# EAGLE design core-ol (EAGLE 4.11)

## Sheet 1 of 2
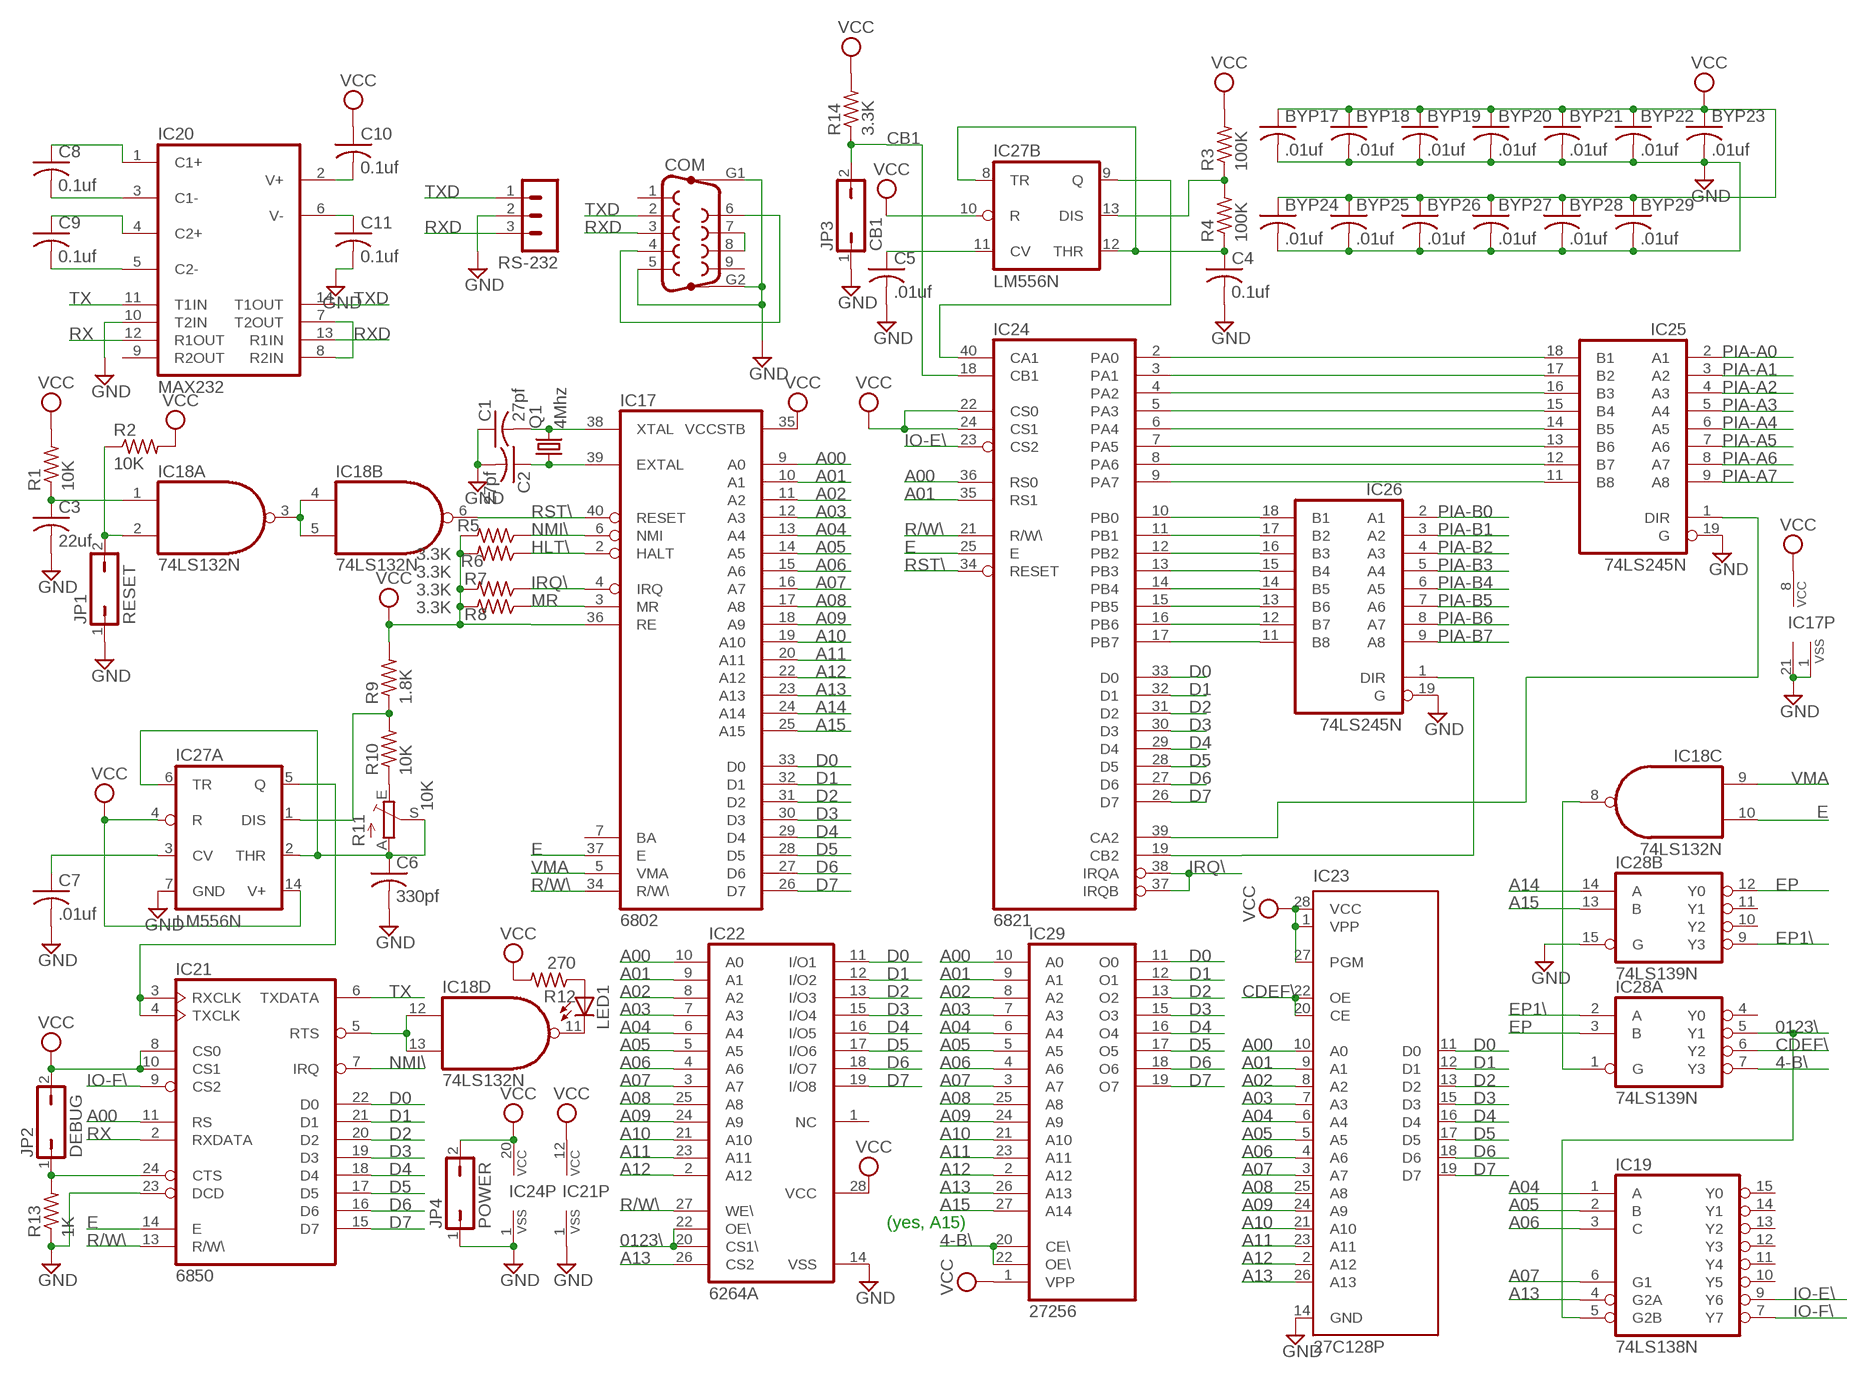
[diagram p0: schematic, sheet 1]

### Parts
BYP17  .01uf  C-US050-025X075  [C050-025X075]
BYP18  .01uf  C-US050-025X075  [C050-025X075]
BYP19  .01uf  C-US050-025X075  [C050-025X075]
BYP20  .01uf  C-US050-025X075  [C050-025X075]
BYP21  .01uf  C-US050-025X075  [C050-025X075]
BYP22  .01uf  C-US050-025X075  [C050-025X075]
BYP23  .01uf  C-US050-025X075  [C050-025X075]
BYP24  .01uf  C-US050-025X075  [C050-025X075]
BYP25  .01uf  C-US050-025X075  [C050-025X075]
BYP26  .01uf  C-US050-025X075  [C050-025X075]
BYP27  .01uf  C-US050-025X075  [C050-025X075]
BYP28  .01uf  C-US050-025X075  [C050-025X075]
BYP29  .01uf  C-US050-025X075  [C050-025X075]
C1  27pf  C-US050-025X075  [C050-025X075]
C2  27pf  C-US050-025X075  [C050-025X075]
C3  22uf  C-US102-043X133  [C102-043X133]
C4  0.1uf  C-US050-025X075  [C050-025X075]
C5  .01uf  C-US050-025X075  [C050-025X075]
C6  330pf  C-US050-025X075  [C050-025X075]
C7  .01uf  C-US050-025X075  [C050-025X075]
C8  0.1uf  C-US050-025X075  [C050-025X075]
C9  0.1uf  C-US050-025X075  [C050-025X075]
C10  0.1uf  C-US050-025X075  [C050-025X075]
C11  0.1uf  C-US050-025X075  [C050-025X075]
COM  F09HP  [F09HP]
IC17  6802  [DIL40]
IC18  74LS132N  74LS00N  [DIL14]
IC19  74LS138N  [DIL16]
IC20  MAX232  [DIL16]
IC21  6850  [DIL24]
IC22  6264A  [DIL28-6]
IC23  27C128P  [DIL28-6]
IC24  6821  [DIL40]
IC25  74LS245N  [DIL20]
IC26  74LS245N  [DIL20]
IC27  LM556N  [DIL14]
IC28  74LS139N  [DIL16]
IC29  27256  [DIL28]
JP1  RESET  JP1Q  [JP1]
JP2  DEBUG  JP1Q  [JP1]
JP3  CB1  JP1Q  [JP1]
JP4  POWER  JP1Q  [JP1]
LED1  LED3MM  [LED3MM]
Q1  4Mhz  CRYTALHC18U-V  [HC18U-V]
R1  10K  R-US_0207/7  [0207/7]
R2  10K  R-US_0207/7  [0207/7]
R3  100K  R-US_0207/7  [0207/7]
R4  100K  R-US_0207/7  [0207/7]
R5  3.3K  R-US_0207/7  [0207/7]
R6  3.3K  R-US_0207/7  [0207/7]
R7  3.3K  R-US_0207/7  [0207/7]
R8  3.3K  R-US_0207/7  [0207/7]
R9  1.8K  R-US_0207/7  [0207/7]
R10  10K  R-US_0207/7  [0207/7]
R11  10K  TRIM_EU-B90P  [SP19L]
R12  270  R-US_0207/7  [0207/7]
R13  1K  R-US_0207/7  [0207/7]
R14  3.3K  R-US_0207/7  [0207/7]
RS-232  MA03-1  [MA03-1]

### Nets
4-B\: IC28.7(A:Y3) IC29.20(CE\) IC29.22(OE\)
0123\: IC19.5(G2B) IC22.20(CS1\) IC22.22(OE\) IC28.5(A:Y1)
A00: IC17.9(A0) IC21.11(RS) IC22.10(A0) IC23.10(A0) IC24.36(RS0) IC29.10(A0)
A01: IC17.10(A1) IC22.9(A1) IC23.9(A1) IC24.35(RS1) IC29.9(A1)
A02: IC17.11(A2) IC22.8(A2) IC23.8(A2) IC29.8(A2)
A03: IC17.12(A3) IC22.7(A3) IC23.7(A3) IC29.7(A3)
A04: IC17.13(A4) IC19.1(A) IC22.6(A4) IC23.6(A4) IC29.6(A4)
A05: IC17.14(A5) IC19.2(B) IC22.5(A5) IC23.5(A5) IC29.5(A5)
A06: IC17.15(A6) IC19.3(C) IC22.4(A6) IC23.4(A6) IC29.4(A6)
A07: IC17.16(A7) IC19.6(G1) IC22.3(A7) IC23.3(A7) IC29.3(A7)
A08: IC17.17(A8) IC22.25(A8) IC23.25(A8) IC29.25(A8)
A09: IC17.18(A9) IC22.24(A9) IC23.24(A9) IC29.24(A9)
A10: IC17.19(A10) IC22.21(A10) IC23.21(A10) IC29.21(A10)
A11: IC17.20(A11) IC22.23(A11) IC23.23(A11) IC29.23(A11)
A12: IC17.22(A12) IC22.2(A12) IC23.2(A12) IC29.2(A12)
A13: IC17.23(A13) IC19.4(G2A) IC22.26(CS2) IC23.26(A13) IC29.26(A13)
A14: IC17.24(A14) IC28.14(B:A)
A15: IC17.25(A15) IC28.13(B:B) IC29.27(A14)
CB1: IC24.18(CB1) JP3.2 R14.1
CDEF\: IC23.20(CE) IC23.22(OE) IC28.6(A:Y2)
D0: IC17.33(D0) IC21.22(D0) IC22.11(I/O1) IC23.11(D0) IC24.33(D0) IC29.11(O0)
D1: IC17.32(D1) IC21.21(D1) IC22.12(I/O2) IC23.12(D1) IC24.32(D1) IC29.12(O1)
D2: IC17.31(D2) IC21.20(D2) IC22.13(I/O3) IC23.13(D2) IC24.31(D2) IC29.13(O2)
D3: IC17.30(D3) IC21.19(D3) IC22.15(I/O4) IC23.15(D3) IC24.30(D3) IC29.15(O3)
D4: IC17.29(D4) IC21.18(D4) IC22.16(I/O5) IC23.16(D4) IC24.29(D4) IC29.16(O4)
D5: IC17.28(D5) IC21.17(D5) IC22.17(I/O6) IC23.17(D5) IC24.28(D5) IC29.17(O5)
D6: IC17.27(D6) IC21.16(D6) IC22.18(I/O7) IC23.18(D6) IC24.27(D6) IC29.18(O6)
D7: IC17.26(D7) IC21.15(D7) IC22.19(I/O8) IC23.19(D7) IC24.26(D7) IC29.19(O7)
E: IC17.37(E) IC18.10(C:I1) IC21.14(E) IC24.25(E)
EP: IC28.3(A:B) IC28.12(B:Y0)
EP1\: IC28.2(A:A) IC28.9(B:Y3)
GND [Power]: BYP17.2 BYP18.2 BYP19.2 BYP20.2 BYP21.2 BYP22.2 BYP23.2 BYP24.2 BYP25.2 BYP26.2 BYP27.2 BYP28.2 BYP29.2 C1.1 C2.2 C3.2 C4.2 C5.2 C6.2 C7.2 C11.2 COM.5 COM.G1 COM.G2 IC17.1(VSS) IC17.21(VSS) IC20.10(T2IN) IC21.1(VSS) IC21.23(DCD) IC22.14(VSS) IC23.14(GND) IC24.1(VSS) IC25.19(G) IC26.19(G) IC27.7(A:GND) IC28.15(B:G) JP1.1 JP3.1 JP4.1 R13.1 RS-232.2 ; also sheet 2
HLT\: IC17.2(HALT) R5.1
IO-E\: IC19.9(Y6) IC24.23(CS2)
IO-F\: IC19.7(Y7) IC21.9(CS2)
IRQ\: IC17.4(IRQ) IC24.37(IRQB) IC24.38(IRQA) R7.1
MR: IC17.3(MR) R8.1
N$1: COM.4 COM.6
N$3: C2.1 IC17.39(EXTAL) Q1.1
N$4: C1.2 IC17.38(XTAL) Q1.2
N$5: IC24.2(PA0) IC25.18(B1)
N$6: IC18.3(A:O) IC18.4(B:I0) IC18.5(B:I1)
N$21: C3.1 IC18.1(A:I0) R1.1
N$22: IC18.2(A:I1) JP1.2 R2.1
N$23: IC21.3(RXCLK) IC21.4(TXCLK) IC27.5(A:Q)
N$24: IC24.10(PB0) IC26.18(B1)
N$25: IC24.11(PB1) IC26.17(B2)
N$27: C6.1 IC27.2(A:THR) IC27.6(A:TR) R11.A R11.S
N$28: IC27.1(A:DIS) R9.1 R10.2
N$94: IC24.12(PB2) IC26.16(B3)
N$124: IC24.13(PB3) IC26.15(B4)
N$125: IC24.14(PB4) IC26.14(B5)
N$126: IC24.15(PB5) IC26.13(B6)
N$127: IC24.16(PB6) IC26.12(B7)
N$128: IC24.17(PB7) IC26.11(B8)
N$129: IC24.3(PA1) IC25.17(B2)
N$130: IC24.4(PA2) IC25.16(B3)
N$131: IC24.5(PA3) IC25.15(B4)
N$132: IC24.6(PA4) IC25.14(B5)
N$133: IC24.7(PA5) IC25.13(B6)
N$134: IC24.8(PA6) IC25.12(B7)
N$135: IC24.9(PA7) IC25.11(B8)
N$136: IC24.19(CB2) IC26.1(DIR)
N$137: IC24.39(CA2) IC25.1(DIR)
N$138: IC24.40(CA1) IC27.9(B:Q)
N$140: C4.1 IC27.8(B:TR) IC27.12(B:THR) R4.1
N$141: IC27.13(B:DIS) R3.1 R4.2
N$142: C5.1 IC27.11(B:CV)
N$143: R10.1 R11.E
N$145: COM.7 COM.8
N$147: IC18.12(D:I0) IC18.13(D:I1) IC21.5(RTS)
N$148: IC18.11(D:O) LED1.K(C)
N$149: LED1.A R12.1
N$150: IC21.24(CTS) JP2.1 R13.2
N$151: IC18.8(C:O) IC28.1(A:G)
N$153: IC20.7(T2OUT) IC20.8(R2IN)
N$154: C7.1 IC27.3(A:CV)
N$155: C9.2 IC20.5(C2-)
N$156: C9.1 IC20.4(C2+)
N$157: C8.2 IC20.3(C1-)
N$158: C8.1 IC20.1(C1+)
N$159: C11.1 IC20.6(V-)
N$160: C10.2 IC20.2(V+)
NMI\: IC17.6(NMI) IC21.7(IRQ) R6.1
PIA-A0: IC25.2(A1) ; also sheet 2
PIA-A1: IC25.3(A2) ; also sheet 2
PIA-A2: IC25.4(A3) ; also sheet 2
PIA-A3: IC25.5(A4) ; also sheet 2
PIA-A4: IC25.6(A5) ; also sheet 2
PIA-A5: IC25.7(A6) ; also sheet 2
PIA-A6: IC25.8(A7) ; also sheet 2
PIA-A7: IC25.9(A8) ; also sheet 2
PIA-B0: IC26.2(A1) ; also sheet 2
PIA-B1: IC26.3(A2) ; also sheet 2
PIA-B2: IC26.4(A3) ; also sheet 2
PIA-B3: IC26.5(A4) ; also sheet 2
PIA-B4: IC26.6(A5) ; also sheet 2
PIA-B5: IC26.7(A6) ; also sheet 2
PIA-B6: IC26.8(A7) ; also sheet 2
PIA-B7: IC26.9(A8) ; also sheet 2
R/W\: IC17.34(R/W\) IC21.13(R/W\) IC22.27(WE\) IC24.21(R/W\)
RST\: IC17.40(RESET) IC18.6(B:O) IC24.34(RESET)
RX: IC20.12(R1OUT) IC21.2(RXDATA)
RXD: COM.3 IC20.13(R1IN) RS-232.3
TX: IC20.11(T1IN) IC21.6(TXDATA)
TXD: COM.2 IC20.14(T1OUT) RS-232.1
VCC [Power]: BYP17.1 BYP18.1 BYP19.1 BYP20.1 BYP21.1 BYP22.1 BYP23.1 BYP24.1 BYP25.1 BYP26.1 BYP27.1 BYP28.1 BYP29.1 C10.1 IC17.8(VCC) IC17.35(VCCSTB) IC17.36(RE) IC21.8(CS0) IC21.10(CS1) IC21.12(VCC) IC22.28(VCC) IC23.1(VPP) IC23.27(PGM) IC23.28(VCC) IC24.20(VCC) IC24.22(CS0) IC24.24(CS1) IC27.4(A:R) IC27.10(B:R) IC27.14(A:V+) IC29.1(VPP) JP2.2 JP4.2 R1.2 R2.2 R3.2 R5.2 R6.2 R7.2 R8.2 R9.2 R12.2 R14.2 ; also sheet 2
VMA: IC17.5(VMA) IC18.9(C:I0)
Unconnected: COM.1 COM.9 IC17.7(BA) IC19.10(Y5) IC19.11(Y4) IC19.12(Y3) IC19.13(Y2) IC19.14(Y1) IC19.15(Y0) IC20.9(R2OUT) IC22.1(NC) IC28.4(A:Y0) IC28.10(B:Y2) IC28.11(B:Y1)

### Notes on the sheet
- (yes, A15)

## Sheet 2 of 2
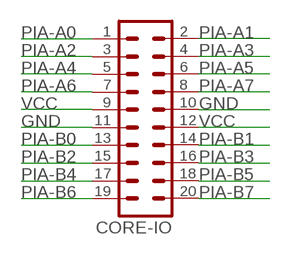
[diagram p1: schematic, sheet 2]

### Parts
CORE-IO  MA10-2  [MA10-2]

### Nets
GND [Power]: CORE-IO.10 CORE-IO.11 ; also sheet 1
PIA-A0: CORE-IO.1 ; also sheet 1
PIA-A1: CORE-IO.2 ; also sheet 1
PIA-A2: CORE-IO.3 ; also sheet 1
PIA-A3: CORE-IO.4 ; also sheet 1
PIA-A4: CORE-IO.5 ; also sheet 1
PIA-A5: CORE-IO.6 ; also sheet 1
PIA-A6: CORE-IO.7 ; also sheet 1
PIA-A7: CORE-IO.8 ; also sheet 1
PIA-B0: CORE-IO.13 ; also sheet 1
PIA-B1: CORE-IO.14 ; also sheet 1
PIA-B2: CORE-IO.15 ; also sheet 1
PIA-B3: CORE-IO.16 ; also sheet 1
PIA-B4: CORE-IO.17 ; also sheet 1
PIA-B5: CORE-IO.18 ; also sheet 1
PIA-B6: CORE-IO.19 ; also sheet 1
PIA-B7: CORE-IO.20 ; also sheet 1
VCC [Power]: CORE-IO.9 CORE-IO.12 ; also sheet 1

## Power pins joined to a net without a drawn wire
GND: IC18.7(P:GND) IC19.8(GND) IC20.15(GND) IC25.10(GND) IC26.10(GND) IC28.8(P:GND) IC29.14(GND)
VCC: IC18.14(P:VCC) IC19.16(VCC) IC20.16(VCC) IC25.20(VCC) IC26.20(VCC) IC28.16(P:VCC) IC29.28(VCC)

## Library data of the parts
BYP17-BYP29 C1-C11 = rcl:C-US: CAPACITOR, American symbol
COM = con-subd:F09HP: SUB-D
CORE-IO = con-lstb:MA10-2: PIN HEADER
IC17 = micro-motorola:6802: MICROCONTROLLER/MEMORY DEVICE
IC18 = 74xx-us:74*00: Quad 2-input NAND gate
IC19 = 74xx-us:74*138: 3-line to 8-line DECODER/DEMULTIPLEXER
IC20 = maxim:MAX232: RS232 TRANSEIVER
IC21 = micro-motorola:6850: MICROCONTROLLER/MEMORY DEVICE
IC22 = memory-hitachi:6264A: MEMORY
IC23 = microchip:27*128: CMOS EPROM 128 K (16 K x 8)
IC24 = micro-motorola:6821: MICROCONTROLLER/MEMORY DEVICE
IC25 IC26 = 74xx-us:74*245: Octal BUS TRANSCEIVER, 3-state
IC27 = linear:*556: Dual TIMER
IC28 = 74xx-us:74*139: Dual 2-line to 4-line DECODER/DEMULTIPLEXER
IC29 = memory:27256: MEMORY
JP1-JP4 = jumper:JP1Q: JUMPER
LED1 = led:LED: LED
Q1 = crystal:CRYTAL: CRYSTAL
R1-R10 R12-R14 = rcl:R-US_: RESISTOR, American symbol
R11 = pot:TRIM_EU-: POTENTIOMETER
RS-232 = con-lstb:MA03-1: PIN HEADER

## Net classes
1 Power: width 0.508 mm, drill 0.254 mm, clearance 0.254 mm

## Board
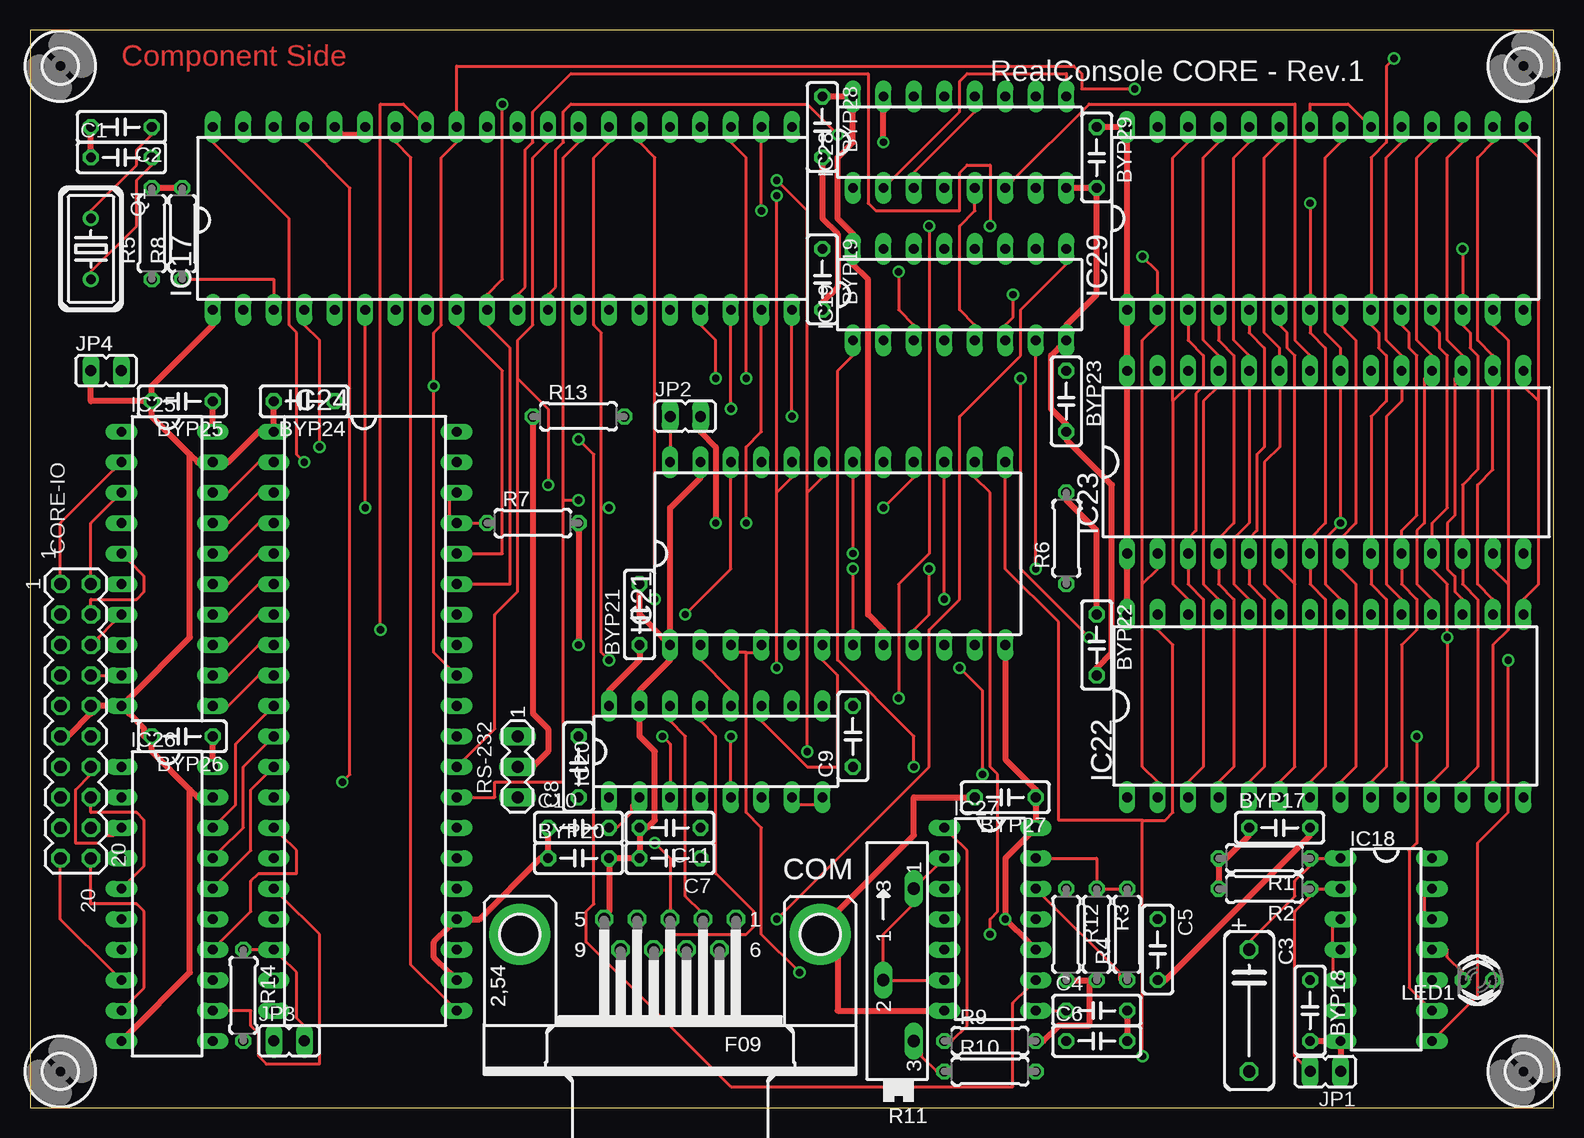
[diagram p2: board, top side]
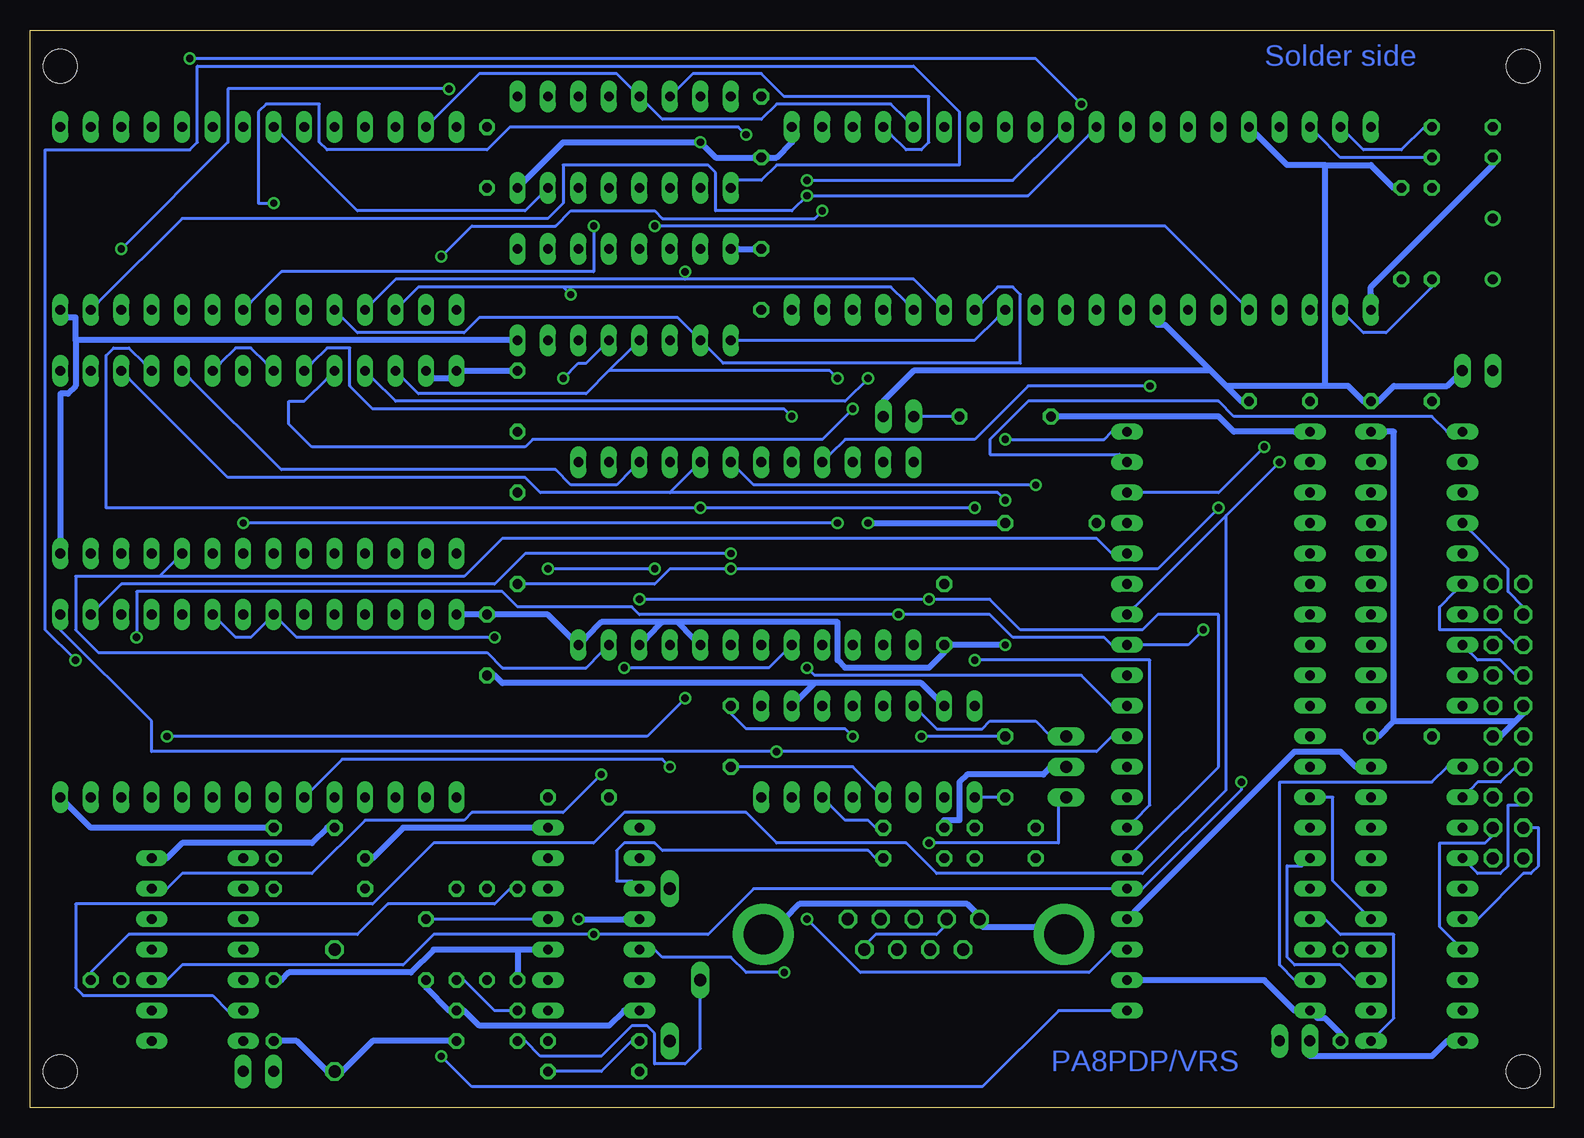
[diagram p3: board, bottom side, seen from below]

Size 126.98 x 89.84 mm. Coordinates in mm from the lower left corner, seen from the top.
Outline: 0,0 126.98,0 126.98,89.84 0,89.84 0,0
Copper layers (1*16): Top 0.035mm / dielectric 1.5mm / Bottom 0.035mm
Design rules "olimex10mil": minimum track width 10mil, minimum drill 24mil, track to track 10mil, track to pad 10mil, pad to pad 10mil, via to via 10mil, smd to smd 10mil, copper to edge 40mil, drill to drill 10mil, minimum pad ring 10mil, minimum via ring 8mil, stop-mask expansion 0mil, vias tented up to drill 0mil, thermal gap 10mil

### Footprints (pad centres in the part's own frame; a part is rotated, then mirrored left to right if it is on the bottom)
C050-025X075 = drill 0.813 octagon: 1 -2.54,0; 2 2.54,0
C102-043X133 = drill 1.016 octagon: 1 -5.08,0; 2 5.08,0
F09HP = drill 1.016 octagon: 1 -5.486,-1.27; 2 -2.743,-1.27; 3 0,-1.27; 4 2.743,-1.27; 5 5.486,-1.27; 6 -4.115,1.27; 7 -1.372,1.27; 8 1.372,1.27; 9 4.115,1.27 | drill 3.302 pad 5.08 round: G1 -12.522,0; G2 12.522,0
MA10-2 = drill 1.016 octagon: 1 -11.43,-1.27; 2 -11.43,1.27; 3 -8.89,-1.27; 4 -8.89,1.27; 5 -6.35,-1.27; 6 -6.35,1.27; 7 -3.81,-1.27; 8 -3.81,1.27; 9 -1.27,-1.27; 10 -1.27,1.27; 11 1.27,-1.27; 12 1.27,1.27; 13 3.81,-1.27; 14 3.81,1.27; 15 6.35,-1.27; 16 6.35,1.27; 17 8.89,-1.27; 18 8.89,1.27; 19 11.43,-1.27; 20 11.43,1.27
DIL40 = drill 0.813 long: 1 -24.13,-7.62; 2 -21.59,-7.62; 3 -19.05,-7.62; 4 -16.51,-7.62; 5 -13.97,-7.62; 6 -11.43,-7.62; 7 -8.89,-7.62; 8 -6.35,-7.62; 9 -3.81,-7.62; 10 -1.27,-7.62; 11 1.27,-7.62; 12 3.81,-7.62; 13 6.35,-7.62; 14 8.89,-7.62; 15 11.43,-7.62; 16 13.97,-7.62; 17 16.51,-7.62; 18 19.05,-7.62; 19 21.59,-7.62; 20 24.13,-7.62; 21 24.13,7.62; 22 21.59,7.62; 23 19.05,7.62; 24 16.51,7.62; 25 13.97,7.62; 26 11.43,7.62; 27 8.89,7.62; 28 6.35,7.62; 29 3.81,7.62; 30 1.27,7.62; 31 -1.27,7.62; 32 -3.81,7.62; 33 -6.35,7.62; 34 -8.89,7.62; 35 -11.43,7.62; 36 -13.97,7.62; 37 -16.51,7.62; 38 -19.05,7.62; 39 -21.59,7.62; 40 -24.13,7.62
DIL14 = drill 0.813 long: 1 -7.62,-3.81; 2 -5.08,-3.81; 3 -2.54,-3.81; 4 0,-3.81; 5 2.54,-3.81; 6 5.08,-3.81; 7 7.62,-3.81; 8 7.62,3.81; 9 5.08,3.81; 10 2.54,3.81; 11 0,3.81; 12 -2.54,3.81; 13 -5.08,3.81; 14 -7.62,3.81
DIL16 = drill 0.813 long: 1 -8.89,-3.81; 2 -6.35,-3.81; 3 -3.81,-3.81; 4 -1.27,-3.81; 5 1.27,-3.81; 6 3.81,-3.81; 7 6.35,-3.81; 8 8.89,-3.81; 9 8.89,3.81; 10 6.35,3.81; 11 3.81,3.81; 12 1.27,3.81; 13 -1.27,3.81; 14 -3.81,3.81; 15 -6.35,3.81; 16 -8.89,3.81
DIL24 = drill 0.813 long: 1 -13.97,-7.62; 2 -11.43,-7.62; 3 -8.89,-7.62; 4 -6.35,-7.62; 5 -3.81,-7.62; 6 -1.27,-7.62; 7 1.27,-7.62; 8 3.81,-7.62; 9 6.35,-7.62; 10 8.89,-7.62; 11 11.43,-7.62; 12 13.97,-7.62; 13 13.97,7.62; 14 11.43,7.62; 15 8.89,7.62; 16 6.35,7.62; 17 3.81,7.62; 18 1.27,7.62; 19 -1.27,7.62; 20 -3.81,7.62; 21 -6.35,7.62; 22 -8.89,7.62; 23 -11.43,7.62; 24 -13.97,7.62
DIL28-6 = drill 0.813 long: 1 -16.51,-7.62; 2 -13.97,-7.62; 3 -11.43,-7.62; 4 -8.89,-7.62; 5 -6.35,-7.62; 6 -3.81,-7.62; 7 -1.27,-7.62; 8 1.27,-7.62; 9 3.81,-7.62; 10 6.35,-7.62; 11 8.89,-7.62; 12 11.43,-7.62; 13 13.97,-7.62; 14 16.51,-7.62; 15 16.51,7.62; 16 13.97,7.62; 17 11.43,7.62; 18 8.89,7.62; 19 6.35,7.62; 20 3.81,7.62; 21 1.27,7.62; 22 -1.27,7.62; 23 -3.81,7.62; 24 -6.35,7.62; 25 -8.89,7.62; 26 -11.43,7.62; 27 -13.97,7.62; 28 -16.51,7.62
DIL20 = drill 0.813 long: 1 -11.43,-3.81; 2 -8.89,-3.81; 3 -6.35,-3.81; 4 -3.81,-3.81; 5 -1.27,-3.81; 6 1.27,-3.81; 7 3.81,-3.81; 8 6.35,-3.81; 9 8.89,-3.81; 10 11.43,-3.81; 11 11.43,3.81; 12 8.89,3.81; 13 6.35,3.81; 14 3.81,3.81; 15 1.27,3.81; 16 -1.27,3.81; 17 -3.81,3.81; 18 -6.35,3.81; 19 -8.89,3.81; 20 -11.43,3.81
DIL28 = drill 0.813 long: 1 -16.51,-7.62; 2 -13.97,-7.62; 3 -11.43,-7.62; 4 -8.89,-7.62; 5 -6.35,-7.62; 6 -3.81,-7.62; 7 -1.27,-7.62; 8 1.27,-7.62; 9 3.81,-7.62; 10 6.35,-7.62; 11 8.89,-7.62; 12 11.43,-7.62; 13 13.97,-7.62; 14 16.51,-7.62; 15 16.51,7.62; 16 13.97,7.62; 17 11.43,7.62; 18 8.89,7.62; 19 6.35,7.62; 20 3.81,7.62; 21 1.27,7.62; 22 -1.27,7.62; 23 -3.81,7.62; 24 -6.35,7.62; 25 -8.89,7.62; 26 -11.43,7.62; 27 -13.97,7.62; 28 -16.51,7.62
JP1 = drill 0.914 long: 1 0,-1.27; 2 0,1.27
LED3MM = drill 0.813 octagon: A -1.27,0; K 1.27,0
HC18U-V = drill 0.813 round: 1 -2.54,0; 2 2.54,0
0207/7 = drill 0.813 octagon: 1 -3.81,0; 2 3.81,0
SP19L = drill 1.016 long: A 5.715,-1.27; E -6.985,-1.27; S -1.905,1.27
MA03-1 = drill 1.016 long: 1 -2.54,0; 2 0,0; 3 2.54,0
2,8 = hole 2.8: 0,0

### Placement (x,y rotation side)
BYP17  104.14,23.33 0 top
BYP18  106.68,8.09 270 top
BYP19  66.04,69.05 270 top
BYP20  45.71,20.79 0 top
BYP21  50.79,41.11 90 top
BYP22  88.9,38.57 270 top
BYP23  86.36,58.89 270 top
BYP24  22.86,58.89 180 top
BYP25  12.69,58.89 180 top
BYP26  12.69,30.95 180 top
BYP27  81.28,25.87 180 top
BYP28  66.04,81.75 270 top
BYP29  88.9,79.21 270 top
C1  7.62,79.21 0 top
C2  7.62,81.75 180 top
C3  101.59,8.09 270 top
C4  88.9,8.09 0 top
C5  93.98,13.17 270 top
C6  88.9,5.55 0 top
C7  53.34,20.79 180 top
C8  45.71,28.41 90 top
C9  68.58,30.95 90 top
C10  45.71,23.33 0 top
C11  53.34,23.33 180 top
COM  53.34,14.44 180 top
CORE-IO  3.81,32.22 270 top
IC17  39.36,74.13 0 top
IC18  113.03,13.17 270 top
IC19  77.47,67.78 0 top
IC20  57.14,29.68 0 top
IC21  67.31,46.19 0 top
IC22  107.95,33.49 0 top
IC23  107.95,53.81 0 top
IC24  27.94,32.22 270 top
IC25  11.42,44.92 270 top
IC26  11.42,16.98 270 top
IC27  80.01,15.71 270 top
IC28  77.47,80.48 0 top
IC29  107.95,74.13 0 top
JP1  107.95,3.01 90 top
JP2  54.6,57.62 270 top
JP3  21.59,5.55 270 top
JP4  6.34,61.43 270 top
LED1  120.65,10.63 180 top
Q1  5.08,71.59 270 top
R1  102.87,20.79 180 top
R2  102.87,18.25 180 top
R3  88.9,14.44 270 top
R4  91.44,14.44 90 top
R5  10.15,72.86 90 top
R6  86.36,47.46 90 top
R7  41.9,48.73 0 top
R8  12.69,72.86 90 top
R9  80.01,5.55 0 top
R10  80.01,3.01 0 top
R11  72.39,12.54 90 top
R12  86.36,14.44 270 top
R13  45.71,57.62 0 top
R14  17.78,9.36 270 top
RS-232  40.63,28.41 270 top
U$3  [2,8]  2.54,86.83 0 top
U$4  [2,8]  2.54,3.01 0 top
U$5  [2,8]  124.45,86.83 0 top
U$6  [2,8]  124.45,3.01 0 top

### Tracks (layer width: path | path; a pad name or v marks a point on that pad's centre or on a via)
4-B\
  Top 0.254: IC29.20 111.12,82.39 109.85,83.66 106.68,83.66 106.68,83.02 IC29.22
  Bottom 0.254: IC28.7 84.45,76.03 85.72,74.77 99.69,74.77 106.04,81.11 IC29.22
0123\  (via drill 0.61)
  Top 0.254: IC19.5 78.73,65.24 77.47,66.51 77.47,73.5 78.73,74.77 78.73,75.4 IC28.5 | v88.26,39.2 82.55,44.92 v82.55,60.8
  Bottom 0.254: IC22.20 111.12,40.48 109.85,39.2 108.58,39.2 107.31,40.48 IC22.22 106.04,40.48 104.77,39.2 v88.26,39.2 | v82.55,60.8 81.28,62.06 80.64,62.06 79.37,63.34 IC19.5
A00
  Top 0.254: IC24.36 36.82,46.19 39.36,46.19 39.36,61.43 35.55,65.24 IC17.9 | IC22.10 114.3,27.14 114.3,38.57 115.56,39.84 115.56,42.38 114.3,43.65 114.3,44.92 IC23.10 114.3,47.46 114.3,48.09 115.56,49.37 115.56,62.7 114.93,63.34 114.93,64.61 114.3,65.24 IC29.10
  Bottom 0.254: 116.2,44.28 123.19,44.28 123.19,39.84 121.28,37.94 88.9,37.94 87.62,36.66 80.64,36.66 79.37,37.94 IC21.11 | 116.2,44.28 114.93,45.55 IC23.10 | 116.2,44.28 90.8,44.28 87.62,47.46 38.09,47.46 36.82,46.19 IC24.36
A01  (via drill 0.61)
  Top 0.254: IC24.35 36.82,43.65 40,43.65 40,63.34 38.09,65.24 IC17.10 38.09,67.78 39.36,69.05 v39.36,83.66 | IC22.9 111.76,27.14 113.03,28.41 113.03,42.38 111.76,43.65 111.76,44.92 IC23.9 111.76,47.46 111.76,57.62 113.03,58.89 113.03,62.7 112.39,63.34 112.39,64.61 111.76,65.24 IC29.9 111.76,67.78 111.76,79.21 113.03,80.48 113.03,86.83 v113.66,87.47
  Bottom 0.254: v39.36,83.66 43.17,87.47 v113.66,87.47
A02  (via drill 0.61)
  Top 0.254: IC22.8 109.22,27.14 110.48,28.41 110.48,43.65 109.22,44.92 IC23.8 109.22,47.46 110.48,48.73 110.48,63.97 109.22,65.24 IC29.8 | v80.01,73.5 80.01,78.58 78.1,78.58 77.47,77.94 77.47,74.77 70.48,74.77 69.84,75.4 69.84,86.19 45.08,86.19 41.9,83.02 41.9,80.48 41.27,79.84 41.27,68.41 40.63,67.78 IC17.11
  Bottom 0.254: v80.01,73.5 80.01,69.69 106.04,69.69 108.58,67.14 IC29.8
A03  (via drill 0.61)
  Top 0.254: IC22.7 106.68,27.14 107.95,28.41 107.95,42.38 106.68,43.65 106.68,44.92 IC23.7 106.68,47.46 107.95,48.73 107.95,63.34 106.68,64.61 106.68,65.24 IC29.7 106.68,67.78 v106.68,75.4 | v67.31,81.11 64.77,83.66 45.08,83.66 44.45,83.02 44.45,80.48 43.81,79.84 43.81,68.41 43.17,67.78 IC17.12
  Bottom 0.254: v67.31,81.11 67.94,81.75 86.99,81.75 88.9,79.84 102.23,79.84 102.87,80.48 102.87,83.66 107.31,83.66 107.95,83.02 107.95,75.4 v106.68,75.4
A04  (via drill 0.61)
  Top 0.254: 105.41,43.65 105.41,28.41 104.14,27.14 IC22.6 | 105.41,43.65 104.14,44.92 IC23.6 | 105.41,43.65 105.41,62.7 104.77,63.34 104.77,64.61 104.14,65.24 IC29.6 | v73.66,28.41 73.66,30.95 67.31,37.3 67.31,61.43 68.58,62.7 IC19.1
  Bottom 0.254: IC17.13 46.35,65.88 48.25,63.97 67.94,63.97 IC19.1 | v73.66,28.41 74.29,29.04 100.96,29.04 103.5,26.5 IC22.6
A05
  Top 0.254: IC22.5 101.59,27.14 102.87,28.41 102.87,42.38 101.59,43.65 101.59,44.92 IC23.5 101.59,47.46 102.23,48.09 102.23,54.45 102.87,55.08 102.87,63.34 101.59,64.61 101.59,65.24 IC29.5
  Bottom 0.254: IC29.5 100.96,65.88 99.69,64.61 90.8,64.61 89.53,65.88 73.02,65.88 71.75,64.61 IC19.2 70.48,63.34 69.21,62.06 44.45,62.06 44.45,67.78 45.08,68.41 46.35,68.41 47.62,67.14 IC17.14
A06  (via drill 0.61)
  Top 0.254: IC22.4 99.06,27.14 100.33,28.41 100.33,42.38 99.06,43.65 99.06,44.92 IC23.4 99.06,47.46 100.33,48.73 100.33,62.7 99.06,63.97 99.06,65.24 IC29.4 | v72.39,69.69 72.39,66.51 73.66,65.24 IC19.3
  Bottom 0.254: 72.39,69.05 96.52,69.05 98.42,67.14 IC29.4 | 72.39,69.05 53.34,69.05 51.43,67.14 IC17.15 | 72.39,69.05 v72.39,69.69
A07  (via drill 0.61)
  Top 0.254: IC22.3 96.52,27.14 97.79,28.41 97.79,42.38 96.52,43.65 96.52,44.92 IC23.3 96.52,47.46 97.15,48.09 97.15,59.52 97.79,60.16 97.79,62.7 96.52,63.97 96.52,65.24 IC29.3 | v81.91,67.78 81.91,65.88 81.28,65.24 IC19.6
  Bottom 0.254: 82.55,68.41 v81.91,67.78 | 82.55,68.41 94.61,68.41 95.88,67.14 IC29.3 | 82.55,68.41 55.24,68.41 53.97,67.14 IC17.16
A08  (via drill 0.61)
  Top 0.254: IC22.25 99.06,42.38 97.79,43.65 97.79,58.89 99.06,60.16 IC23.25 99.06,62.7 97.79,63.97 97.79,79.21 99.06,80.48 IC29.25 | v57.14,60.8 57.14,63.97 55.88,65.24 IC17.17
  Bottom 0.254: v57.14,60.8 59.05,58.89 96.52,58.89 98.42,60.8 IC23.25
A09  (via drill 0.61)
  Top 0.254: IC22.24 101.59,42.38 100.33,43.65 100.33,47.46 101.59,48.73 101.59,60.16 IC23.24 101.59,62.7 100.33,63.97 100.33,79.21 101.59,80.48 IC29.24 | v58.41,58.25 58.41,65.24 IC17.18
  Bottom 0.254: v58.41,58.25 60.95,55.71 85.09,55.71 85.72,55.08 103.5,55.08 105.41,56.98 105.41,58.89 104.14,58.89 102.23,60.8 IC23.24
A10  (via drill 0.61)
  Top 0.254: IC22.21 109.22,42.38 107.95,43.65 107.95,47.46 v109.22,48.73 109.22,60.16 IC23.21 109.22,62.7 109.22,63.34 107.95,64.61 107.95,79.21 109.22,80.48 IC29.21 | v59.68,48.73 59.68,55.08 60.95,56.35 60.95,65.24 IC17.19
  Bottom 0.254: v59.68,48.73 v109.22,48.73
A11  (via drill 0.61)
  Top 0.254: IC22.23 104.14,42.38 102.87,43.65 102.87,53.81 104.14,55.08 104.14,60.16 IC23.23 104.14,62.7 104.14,63.34 102.87,64.61 102.87,79.21 104.14,80.48 IC29.23 | v63.49,57.62 63.49,65.24 IC17.20
  Bottom 0.254: v63.49,57.62 64.13,58.25 98.42,58.25 100.33,60.16 100.33,63.34 102.23,63.34 103.5,62.06 IC23.23
A12  (via drill 0.61)
  Top 0.254: 92.7,43.65 92.7,28.41 93.98,27.14 IC22.2 | 92.7,43.65 93.98,44.92 IC23.2 | 92.7,43.65 92.7,63.97 93.98,65.24 IC29.2 93.98,67.78 93.98,69.69 v92.7,70.95 | v60.95,74.77 60.95,80.48 IC17.22
  Bottom 0.254: v60.95,74.77 61.59,74.13 74.29,74.13 74.93,74.77 81.91,74.77 83.18,73.5 90.17,73.5 v92.7,70.95
A13  (via drill 0.61)
  Top 0.254: 95.25,58.89 95.25,43.65 96.52,42.38 IC22.26 | 95.25,58.89 96.52,60.16 IC23.26 | v59.68,60.8 59.68,79.21 58.41,80.48 IC17.23 | 95.25,58.89 95.25,79.21 96.52,80.48 IC29.26
  Bottom 0.254: 78.73,61.43 80.64,59.52 94.61,59.52 95.88,60.8 IC23.26 | 78.73,61.43 76.83,63.34 IC19.4 | v59.68,60.8 60.32,61.43 78.73,61.43
A14
  Bottom 0.254: IC17.24 55.24,81.11 53.97,79.84 52.7,79.84 52.06,80.48 52.06,84.29 64.13,84.29 66.04,86.19 71.75,86.19 73.02,84.92 IC28.14
A15
  Bottom 0.254: IC17.25 53.97,82.39 55.24,83.66 64.77,83.66 66.04,82.39 74.29,82.39 75.56,83.66 IC28.13 76.83,84.92 78.1,86.19 89.53,86.19 93.34,82.39 IC29.27
CB1
  Top 0.254: R14.1 18.41,13.17 19.05,13.17 IC24.18 20.95,12.54 22.22,11.27 22.22,7.46 22.86,6.82 JP3.2
CDEF\
  Top 0.254: IC28.6 81.91,77.3 88.26,83.66 105.41,83.66 105.41,63.97 106.68,62.7 IC23.22
  Bottom 0.254: IC23.22 107.31,62.06 108.58,63.34 109.85,63.34 111.12,62.06 IC23.20
D0  (via drill 0.61)
  Top 0.254: IC22.11 116.84,27.14 118.11,28.41 v118.11,39.2 118.11,43.65 116.84,44.92 IC23.11 116.84,47.46 116.84,48.73 118.11,50 118.11,62.7 117.47,63.34 117.47,64.61 116.84,65.24 IC29.11 | v54.6,41.11 58.41,44.92 58.41,52.54 IC21.22 | v29.21,39.84 29.21,83.66 31.11,83.66 32.38,82.39 IC17.33
  Bottom 0.254: v29.21,39.84 30.48,38.57 34.28,38.57 IC24.33 36.82,38.57 37.46,39.2 45.08,39.2 46.98,41.11 v54.6,41.11 76.2,41.11 76.83,41.74 86.36,41.74 87.62,43.02 118.11,43.02 v118.11,39.2
D1  (via drill 0.61)
  Top 0.254: IC22.12 119.38,27.14 120.65,28.41 120.65,42.38 119.38,43.65 119.38,44.92 IC23.12 119.38,47.46 119.38,51.91 120.65,53.17 120.65,62.7 120.01,63.34 120.01,64.61 119.38,65.24 IC29.12 119.38,67.78 v119.38,71.59 | IC24.32 34.92,36.66 33.65,37.94 v33.65,60.16 33.65,64.61 34.28,65.24 34.28,79.21 35.55,80.48 IC17.32 35.55,83.02 35.55,86.83 86.99,86.83 87.62,86.19 87.62,84.92 v92.07,84.92
  Bottom 0.254: v33.65,60.16 43.81,60.16 48.25,55.71 59.05,55.71 60.32,54.45 IC21.21 | v119.38,71.59 110.48,80.48 110.48,84.92 v92.07,84.92
D2  (via drill 0.61)
  Top 0.254: 123.19,43.65 123.19,39.84 121.92,38.57 121.92,27.14 IC22.13 | 123.19,43.65 121.92,44.92 IC23.13 | 123.19,43.65 123.19,63.97 121.92,65.24 IC29.13 | v62.22,36.66 62.22,51.27 | 62.22,51.27 63.49,52.54 IC21.20 | 62.22,51.27 v62.22,76.03
  Bottom 0.254: v62.22,36.66 61.59,36.03 39.36,36.03 36.82,33.49 IC24.31 | IC17.31 38.73,81.11 43.81,76.03 v62.22,76.03 63.49,74.77 69.84,74.77 69.84,77.94 70.48,78.58 82.55,78.58 82.55,75.4 83.81,74.13 114.3,74.13 121.28,67.14 IC29.13
D3  (via drill 0.61)
  Top 0.254: 125.73,58.89 125.73,43.65 124.45,42.38 IC22.15 | 125.73,58.89 124.45,60.16 IC23.15 | 125.73,58.89 125.73,79.21 124.45,80.48 IC29.15 | v64.77,29.68 64.77,51.27 | 64.77,51.27 66.04,52.54 IC21.19 | v62.22,77.3 64.77,74.77 64.77,51.27
  Bottom 0.254: IC24.30 36.82,30.95 38.09,29.68 v64.77,29.68 116.84,29.68 116.84,32.22 124.45,39.84 IC22.15 | v62.22,77.3 45.08,77.3 41.27,81.11 IC17.30
D4  (via drill 0.61)
  Top 0.254: IC22.16 121.92,42.38 120.65,43.65 120.65,51.91 121.92,53.17 121.92,60.16 IC23.16 121.92,62.7 120.65,63.97 120.65,79.21 121.92,80.48 IC29.16 | 40.63,60.8 40.63,63.97 41.9,65.24 41.9,79.21 43.17,80.48 IC17.29 | 40.63,60.8 40.63,43.02 38.73,41.11 38.73,31.58 36.19,29.04 IC24.29 | v43.17,51.91 43.17,58.25 40.63,60.8 | v68.58,46.19 68.58,52.54 IC21.18
  Bottom 0.254: v43.17,51.91 66.67,51.91 67.94,53.17 IC21.18 | v68.58,46.19 85.72,46.19 88.26,43.65 119.38,43.65 121.28,41.74 IC22.16
D5  (via drill 0.61)
  Top 0.254: 44.45,50.63 44.45,79.21 45.71,80.48 IC17.28 | 44.45,50.63 44.45,27.14 38.73,27.14 38.73,25.87 36.82,25.87 IC24.28 | IC22.17 119.38,42.38 118.74,43.02 118.74,44.28 118.11,44.92 118.11,48.73 118.74,49.37 118.74,60.8 IC23.17 119.38,62.7 118.11,63.97 118.11,79.21 119.38,80.48 IC29.17 | 44.45,50.63 v45.71,50.63
  Bottom 0.254: 73.66,51.27 71.75,53.17 IC21.17 | 73.66,51.27 84.45,51.27 85.72,52.54 110.48,52.54 118.74,60.8 IC23.17 | v45.71,50.63 46.35,51.27 73.66,51.27
D6  (via drill 0.61)
  Top 0.254: IC22.18 116.84,42.38 115.56,43.65 115.56,48.09 116.2,48.73 116.2,60.8 IC23.18 116.84,62.7 115.56,63.97 115.56,79.21 116.84,80.48 IC29.18 | v48.25,37.3 47.62,37.94 47.62,50 | 47.62,50 47.62,64.61 46.98,65.24 46.98,79.21 48.25,80.48 IC17.27 | v71.12,50 73.66,52.54 IC21.16 | 47.62,50 v48.25,50
  Bottom 0.254: v48.25,37.3 33.65,37.3 33.65,25.23 34.92,23.96 IC24.27 | v48.25,50 v71.12,50 120.65,50 120.65,62.7 120.01,63.34 118.74,63.34 117.47,62.06 IC23.18
D7  (via drill 0.61)
  Top 0.254: IC22.19 114.3,42.38 113.03,43.65 113.03,57.62 114.3,58.89 114.3,60.16 IC23.19 114.3,62.7 113.03,63.97 113.03,79.21 114.3,80.48 IC29.19 | v76.2,42.38 76.2,52.54 IC21.15 | v52.06,42.38 52.06,79.21 50.79,80.48 IC17.26
  Bottom 0.254: v76.2,42.38 v52.06,42.38 46.98,42.38 44.45,39.84 34.28,39.84 33.02,41.11 27.94,41.11 27.94,28.41 34.92,21.42 IC24.26 | IC23.19 113.66,60.8 106.04,53.17 83.18,53.17 81.91,51.91 78.1,51.91 76.83,53.17 IC21.15
E  (via drill 0.61)
  Top 0.254: v26.03,27.14 26.67,27.77 26.67,76.67 22.86,80.48 IC17.37 | v80.01,14.44 80.01,15.71 80.64,16.34 80.64,27.77 80.01,28.41 80.01,51.27 78.73,52.54 IC21.14
  Bottom 0.254: IC18.10 115.56,10.63 114.3,11.9 95.88,11.9 93.34,14.44 v80.01,14.44 70.48,14.44 66.67,18.25 36.82,18.25 IC24.25 34.28,18.25 26.03,26.5 v26.03,27.14
EP
  Top 0.254: IC28.3 73.66,77.94 78.73,83.02 IC28.12
EP1\
  Top 0.254: IC28.2 71.75,77.3 77.47,83.02 77.47,85.56 78.1,86.19 86.36,86.19 86.36,85.56 IC28.9
GND  (via drill 0.61)
  Top 0.508: IC25.10 6.34,33.49 5.71,33.49 CORE-IO.10 5.08,32.85 3.17,30.95 CORE-IO.11 | 13.33,26.5 10.15,29.68 10.15,30.31 BYP26.2 9.52,30.95 9.52,31.58 8.25,32.85 IC25.10 | 13.33,26.5 13.96,25.87 IC26.19 | 13.33,26.5 13.33,11.27 8.25,6.18 IC26.10 | BYP24.2 20.32,58.25 20.32,56.98 IC24.1 19.05,56.35 16.51,53.81 IC25.19 13.96,53.81 13.33,54.45 | C1.1 5.08,79.84 5.08,81.11 C2.2 | BYP25.2 9.52,58.89 5.08,58.89 5.08,60.16 JP4.1 | IC17.1 15.23,65.24 10.15,60.16 10.15,59.52 BYP25.2 | 13.33,54.45 10.15,57.62 10.15,58.25 BYP25.2 | 13.33,54.45 13.33,39.2 8.25,34.12 IC25.10 | IC28.8 86.99,76.67 88.26,76.67 BYP29.2 88.9,76.03 88.9,67.78 86.36,65.24 IC19.8 85.72,63.34 85.09,62.7 85.09,58.25 86.36,56.98 BYP23.2 86.36,55.71 90.17,51.91 90.17,37.94 88.9,36.66 BYP22.2 | BYP19.2 66.04,67.14 67.31,68.41 67.31,72.86 66.04,74.13 66.04,78.58 BYP28.2 | v71.12,80.48 71.12,83.02 IC28.15 | IC27.7 74.93,8.09 67.31,8.09 67.31,12.54 COM.G1 67.31,16.34 73.66,22.7 73.66,25.87 78.1,25.87 BYP27.2 | BYP18.2 107.31,5.55 107.95,5.55 IC18.7 109.22,4.92 109.22,4.28 JP1.1 | C6.2 91.44,6.18 91.44,7.46 C4.2 | BYP17.2 106.68,22.7 94.61,10.63 C5.2 | COM.5 48.25,16.34 48.25,20.15 BYP20.2 48.89,20.79 50.16,20.79 C7.2 50.79,21.42 50.79,22.7 C11.2 51.43,23.33 52.06,23.96 52.06,29.68 50.79,30.95 50.79,32.22 IC20.15 50.79,34.76 53.34,37.3 IC21.1 | BYP21.2 50.79,43.02 50.79,41.11 52.7,39.2 IC21.1 | IC21.23 55.88,52.54 53.34,50 53.34,39.84 IC21.1 | R13.1 41.9,56.98 41.9,32.85 43.17,31.58 43.17,29.68 41.9,28.41 RS-232.2
  Bottom 0.508: IC26.10 8.88,5.55 10.15,4.28 20.32,4.28 JP3.1 | R13.1 41.27,57.62 27.94,57.62 26.67,56.35 21.59,56.35 IC24.1 | C1.1 5.08,78.58 15.23,68.41 15.23,67.78 IC17.1 | 123.19,63.97 123.19,65.88 123.82,65.88 IC29.14 | 123.19,63.97 123.19,60.16 123.82,59.52 124.45,59.52 124.45,47.46 IC23.14 | IC17.21 63.49,80.48 64.77,79.21 65.4,79.21 BYP28.2 66.67,79.21 69.84,79.21 v71.12,80.48 82.55,80.48 85.72,77.3 IC28.8 | 123.19,63.97 86.99,63.97 IC19.8 | BYP18.2 106.04,5.55 104.77,5.55 102.23,3.01 C3.2 100.96,3.01 98.42,5.55 92.07,5.55 C6.2 | C5.2 93.98,10 92.07,8.09 C4.2 90.8,8.09 89.53,6.82 78.73,6.82 77.47,8.09 IC27.7 | IC22.14 123.82,25.23 121.92,23.33 107.31,23.33 BYP17.2 | RS-232.2 41.9,28.41 42.54,27.77 48.89,27.77 49.52,27.14 49.52,23.96 50.79,23.96 C11.2 | COM.G2 43.17,15.08 47.62,15.08 COM.5 48.25,16.34 48.89,16.98 62.86,16.98 64.13,15.71 COM.G1 | 61.59,35.39 62.86,34.12 IC20.10 | 61.59,35.39 52.7,35.39 51.43,34.12 IC20.15 | 61.59,35.39 87.62,35.39 88.26,36.03 BYP22.2
HLT\
  Bottom 0.254: R5.1 10.15,68.41 13.96,64.61 15.87,64.61 17.14,65.88 IC17.2
IO-E\  (via drill 0.61)
  Top 0.254: v62.22,15.71 74.93,28.41 74.93,39.84 77.47,42.38 77.47,57.62 82.55,62.7 82.55,66.51 86.36,70.32 IC19.9
  Bottom 0.254: v62.22,15.71 57.78,11.27 38.73,11.27 36.82,13.17 IC24.23
IO-F\  (via drill 0.61)
  Top 0.254: v74.93,44.92 74.93,41.11 73.66,39.84 IC21.9 | v83.81,44.92 83.81,62.7 IC19.7
  Bottom 0.254: v74.93,44.92 v83.81,44.92
IRQ\  (via drill 0.61)
  Top 0.254: R7.1 37.46,48.73 36.82,48.73 IC24.37 34.92,49.37 34.92,50.63 IC24.38 | v24.12,55.08 24.12,63.97 22.86,65.24 IC17.4
  Bottom 0.254: v24.12,55.08 27.94,51.27 34.28,51.27 IC24.38
MR
  Top 0.254: R8.1 13.33,69.05 20.32,69.05 20.32,67.78 IC17.3
N$1
  Bottom 0.254: COM.4 50.79,15.08 51.43,14.44 56.51,14.44 57.14,13.81 COM.6
N$3
  Top 0.254: Q1.1 5.08,74.77 8.88,78.58 8.88,79.84 10.15,81.11 C2.1
  Bottom 0.254: IC17.39 17.14,81.11 15.87,79.84 12.69,79.84 10.79,81.75 C2.1
N$4
  Top 0.254: Q1.2 5.08,69.69 8.88,73.5 8.88,77.3 10.15,78.58 C1.2
  Bottom 0.254: IC17.38 19.68,81.11 17.78,79.21 10.79,79.21 C1.2
N$5
  Top 0.254: IC25.18 16.51,51.27 19.05,53.81 IC24.2
N$6
  Top 0.254: IC18.5 108.58,11.27 108.58,12.54 IC18.4 108.58,13.81 108.58,15.08 IC18.3
N$21
  Top 0.254: IC18.1 107.95,20.79 107.31,20.79 R1.1 106.68,20.15 105.41,18.88 105.41,17.61 101.59,13.81 C3.1
N$22
  Top 0.254: IC18.2 107.95,18.25 107.31,18.25 R2.1 106.68,17.61 105.41,16.34 105.41,4.28 106.04,3.64 JP1.2
N$23  (via drill 0.61)
  Top 0.254: 59.68,37.94 60.32,37.94 IC21.4 | 59.68,37.94 59.05,37.94 IC21.3 | v64.13,11.27 60.95,14.44 60.95,23.33 59.68,24.6 59.68,37.94
  Bottom 0.254: v64.13,11.27 67.31,11.27 68.58,12.54 74.29,12.54 74.93,13.17 IC27.5
N$24
  Top 0.254: IC26.18 15.87,23.96 17.14,25.23 17.14,30.31 19.68,32.85 IC24.10
N$25
  Top 0.254: IC26.17 15.87,21.42 17.78,23.33 17.78,28.41 19.68,30.31 IC24.11
N$27
  Top 0.254: IC27.2 75.56,20.15 74.29,18.88 R11.A 73.66,16.98 71.12,14.44 71.12,11.9 R11.S 71.75,10.63 74.93,10.63 IC27.6
  Bottom 0.254: C6.1 85.72,5.55 84.45,4.28 79.37,4.28 76.83,6.82 75.56,6.82 74.93,6.18 74.93,3.64 72.39,3.64 71.12,4.92 71.12,9.36 R11.S
N$28
  Top 0.254: IC27.1 76.83,22.7 78.1,21.42 78.1,6.82 76.83,5.55 R9.1
  Bottom 0.254: R9.1 76.83,5.55 79.37,3.01 83.18,3.01 R10.2
N$94
  Top 0.254: IC26.16 15.87,18.88 18.41,21.42 18.41,26.5 19.68,27.77 IC24.12
N$124
  Bottom 0.254: IC26.15 15.87,16.34 18.41,18.88 18.41,25.87 19.05,25.87 IC24.13
N$125
  Top 0.254: IC26.14 15.87,13.81 18.41,16.34 18.41,18.88 19.05,19.52 22.22,19.52 22.22,21.42 20.95,22.7 IC24.14
N$126
  Bottom 0.254: IC26.13 16.51,10.63 17.78,11.9 21.59,11.9 22.22,12.54 22.22,20.15 20.95,20.15 IC24.15
N$127
  Top 0.254: IC26.12 16.51,8.09 18.41,8.09 18.41,6.82 19.05,6.18 19.05,4.28 19.68,3.64 24.12,3.64 24.12,14.44 20.95,17.61 IC24.16
N$128
  Bottom 0.254: IC26.11 14.6,6.18 13.33,7.46 13.33,14.44 17.78,14.44 19.05,15.71 IC24.17
N$129
  Top 0.254: IC25.17 16.51,48.73 19.05,51.27 IC24.3
N$130
  Top 0.254: IC25.16 16.51,46.19 19.05,48.73 IC24.4
N$131
  Top 0.254: IC25.15 16.51,43.65 19.05,46.19 IC24.5
N$132
  Top 0.254: IC25.14 16.51,41.11 19.05,43.65 IC24.6
N$133
  Top 0.254: IC25.13 16.51,38.57 19.05,41.11 IC24.7
N$134
  Top 0.254: IC25.12 16.51,36.03 19.05,38.57 IC24.8
N$135
  Top 0.254: IC25.11 16.51,33.49 19.05,36.03 IC24.9
N$136
  Bottom 0.254: IC24.19 21.59,10.63 22.86,11.9 22.86,27.14 10.15,27.14 8.88,28.41 IC26.1
N$137
  Bottom 0.254: IC25.1 8.88,56.35 10.15,57.62 26.67,57.62 27.94,58.89 43.81,58.89 46.98,55.71 46.98,54.45 36.19,54.45 IC24.39
N$138  (via drill 0.61)
  Top 0.254: v45.71,55.71 46.98,54.45 46.98,16.98 46.35,16.34 46.35,13.81 58.41,1.74 81.91,1.74 81.91,8.73 83.18,10 IC27.9
  Bottom 0.254: v45.71,55.71 37.46,55.71 36.82,56.35 IC24.40
N$140
  Top 0.254: IC27.8 85.09,8.09 85.72,8.09 C4.1 | IC27.12 84.45,17.61 90.8,11.27 90.8,10.63 R4.1
  Bottom 0.254: R4.1 90.8,10.63 88.26,8.09 86.99,8.09 C4.1
N$141
  Top 0.254: R4.2 90.8,18.25 89.53,18.25 R3.1 88.9,18.88 88.9,20.79 85.09,20.79 IC27.13
N$142
  Bottom 0.254: IC27.11 85.09,15.71 93.34,15.71 C5.1
N$143
  Top 0.254: R10.1 75.56,3.01 74.29,4.28 74.29,4.92 R11.E
N$145
  Top 0.254: COM.8 52.7,13.17 53.97,13.17 COM.7
N$147  (via drill 0.61)
  Top 0.254: IC18.12 116.2,16.34 116.2,17.61 IC18.13 | v77.47,36.66 79.37,34.76 v79.37,27.77
  Bottom 0.254: v77.47,36.66 65.4,36.66 64.13,37.94 IC21.5 | v79.37,27.77 82.55,24.6 90.17,24.6 90.8,23.96 99.06,23.96 103.5,19.52 114.3,19.52 115.56,18.25 IC18.13
N$148
  Top 0.254: LED1.K 119.38,11.27 118.11,12.54 118.11,13.17 IC18.11
N$149
  Bottom 0.254: R12.1 86.99,18.25 88.26,16.98 97.15,16.98 99.69,14.44 118.74,14.44 121.92,11.27 LED1.A
N$150
  Top 0.254: IC21.24 53.34,55.08 53.34,56.35 JP2.1
  Bottom 0.254: R13.2 50.16,57.62 52.7,57.62 JP2.1
N$151  (via drill 0.61)
  Top 0.254: v123.19,37.3 123.19,24.6 120.65,22.06 120.65,9.36 117.47,6.18 IC18.8
  Bottom 0.254: v123.19,37.3 125.73,39.84 125.73,79.84 113.66,79.84 113.03,80.48 113.03,86.83 53.34,86.83 49.52,83.02 49.52,78.58 64.77,78.58 66.04,77.3 67.94,77.3 IC28.1
N$153
  Top 0.254: IC20.7 64.13,25.23 65.4,25.23 IC20.8
N$154
  Bottom 0.254: C7.1 56.51,20.79 57.14,21.42 74.29,21.42 74.93,22.06 77.47,22.06 78.1,21.42 78.1,18.88 76.83,18.88 IC27.3
N$155  (via drill 0.61)
  Top 0.254: v58.41,30.95 58.41,27.14 IC20.5
  Bottom 0.254: v58.41,30.95 59.05,31.58 67.31,31.58 68.58,32.85 C9.2
N$156
  Bottom 0.254: IC20.4 56.51,26.5 58.41,28.41 67.94,28.41 C9.1
N$157  (via drill 0.61)
  Top 0.254: v52.7,30.95 53.34,30.31 53.34,27.14 IC20.3
  Bottom 0.254: v52.7,30.95 46.35,30.95 C8.2
N$158
  Bottom 0.254: C8.1 46.35,25.87 47.62,25.87 IC20.1
N$159
  Bottom 0.254: C11.1 56.51,23.33 57.14,23.96 59.05,23.96 60.32,25.23 IC20.6
N$160
  Top 0.254: C10.2 48.89,23.33 50.16,24.6 50.16,25.23 IC20.2
NMI\  (via drill 0.61)
  Top 0.254: v27.94,50 27.94,65.24 IC17.6 | v68.58,44.92 68.58,39.84 IC21.7
  Bottom 0.254: v27.94,50 33.02,44.92 v68.58,44.92 73.66,44.92 74.93,43.65 85.72,43.65 R6.1
PIA-A0
  Top 0.254: IC25.2 6.98,53.17 2.54,48.73 2.54,44.28 CORE-IO.1
PIA-A1
  Top 0.254: IC25.3 6.98,50.63 5.08,48.73 5.08,44.28 CORE-IO.2
PIA-A2
  Bottom 0.254: IC25.4 6.98,48.09 3.81,44.92 3.81,43.02 2.54,41.74 CORE-IO.3
PIA-A3
  Top 0.254: IC25.5 8.25,45.55 9.52,44.28 9.52,43.02 8.88,42.38 5.08,42.38 5.08,41.74 CORE-IO.4
PIA-A4
  Bottom 0.254: IC25.6 8.25,43.02 9.52,41.74 9.52,39.84 4.44,39.84 3.17,38.57 CORE-IO.5
PIA-A5
  Top 0.254: IC25.7 6.98,40.48 5.71,39.2 5.71,38.57 CORE-IO.6
PIA-A6
  Bottom 0.254: IC25.8 6.98,37.94 6.34,37.3 4.44,37.3 3.17,36.03 CORE-IO.7
PIA-A7
  Top 0.254: IC25.9 6.34,36.03 5.71,36.03 CORE-IO.8
PIA-B0
  Bottom 0.254: IC26.2 6.98,26.5 6.34,27.14 4.44,27.14 3.17,28.41 CORE-IO.13
PIA-B1
  Top 0.254: IC26.3 6.98,22.7 6.34,22.7 5.71,22.06 3.81,22.06 3.81,26.5 5.08,27.77 CORE-IO.14
PIA-B2
  Bottom 0.254: IC26.4 6.98,20.15 6.34,19.52 4.44,19.52 3.81,20.15 3.81,25.23 2.54,25.23 CORE-IO.15
PIA-B3
  Top 0.254: IC26.5 8.25,18.88 9.52,20.15 9.52,23.96 8.88,24.6 5.08,24.6 5.08,25.23 CORE-IO.16
PIA-B4
  Bottom 0.254: IC26.6 6.34,15.71 2.54,19.52 1.9,19.52 1.27,20.15 1.27,23.33 1.9,23.33 CORE-IO.17
PIA-B5
  Bottom 0.254: IC26.7 8.25,13.81 9.52,15.08 9.52,22.06 5.71,22.06 5.08,22.7 CORE-IO.18
PIA-B6
  Top 0.254: IC26.8 6.98,11.27 2.54,15.71 2.54,20.15 CORE-IO.19
PIA-B7
  Top 0.254: IC26.9 8.25,8.73 9.52,10 9.52,16.34 8.88,16.98 5.08,16.98 5.08,20.15 CORE-IO.20
R/W\  (via drill 0.61)
  Top 0.254: 92.7,23.96 85.72,23.96 85.72,40.48 81.28,44.92 81.28,52.54 IC21.13 | 92.7,23.96 94.61,23.96 95.25,24.6 95.25,38.57 93.98,39.84 IC22.27 | IC24.21 34.92,8.73 31.75,11.9 31.75,79.21 30.48,80.48 IC17.34 | v92.7,4.28 92.7,23.96
  Bottom 0.254: v92.7,4.28 90.17,1.74 47.62,1.74 41.27,8.09 36.82,8.09 IC24.21
RST\  (via drill 0.61)
  Top 0.254: v22.86,53.81 22.22,54.45 22.22,64.61 21.59,65.24 21.59,74.13 15.23,80.48 IC17.40
  Bottom 0.254: 27.3,49.37 v22.86,53.81 | 27.3,49.37 34.92,41.74 IC24.34 | 27.3,49.37 27.3,26.5 34.28,19.52 51.43,19.52 53.97,22.06 64.77,22.06 67.31,24.6 77.47,24.6 80.01,22.06 93.34,22.06 98.42,16.98 123.19,16.98 123.19,10 122.55,9.36 111.76,9.36 110.48,8.09 IC18.6
RX
  Top 0.254: IC20.12 58.41,34.76 55.88,37.3 IC21.2
RXD  (via drill 0.61)
  Top 0.254: IC20.13 55.88,32.22 57.14,30.95 57.14,19.52 60.32,16.34 60.32,15.08 59.68,14.44 53.34,14.44 53.34,15.08 COM.3 53.34,16.34 53.34,20.79 v52.06,22.06
  Bottom 0.254: v52.06,22.06 41.27,22.06 41.27,25.23 RS-232.3
TX
  Top 0.254: IC20.11 60.95,32.22 64.77,28.41 67.31,28.41 67.31,36.03 66.04,37.3 IC21.6
TXD
  Top 0.254: IC20.14 53.34,32.22 54.6,30.95 54.6,17.61 55.88,16.34 COM.2
  Bottom 0.254: RS-232.1 41.9,30.95 43.17,32.22 46.98,32.22 47.62,31.58 51.43,31.58 52.7,32.85 IC20.14
VCC  (via drill 0.61)
  Top 0.508: C10.1 43.17,22.7 43.17,21.42 BYP20.1 42.54,20.79 37.46,15.71 36.82,15.71 IC24.24 34.92,15.08 33.65,13.81 33.65,12.54 34.92,11.27 IC24.22 | R5.2 10.79,76.67 12.06,76.67 R8.2 | IC17.36 26.03,81.11 27.3,81.11 IC17.35 | IC26.20 15.23,29.04 15.23,30.31 BYP26.1 | IC25.20 15.23,56.98 15.23,58.25 BYP25.1 | R2.2 99.06,18.88 99.06,20.15 R1.2 99.69,20.79 101.59,22.7 BYP17.1 | 88.26,10.63 88.26,6.82 85.72,6.82 84.45,5.55 R9.2 | 88.26,10.63 R3.2 88.26,10.63 | 88.26,10.63 86.99,10.63 R12.2 | IC27.10 83.18,13.81 v81.28,15.71 81.28,20.79 83.18,22.7 IC27.14 83.81,23.96 83.81,25.23 BYP27.1 83.81,26.5 81.28,29.04 81.28,37.3 IC21.12 | BYP29.1 89.53,81.75 90.8,81.75 IC29.28 91.44,80.48 91.44,67.78 IC29.1 91.44,65.24 91.44,62.7 IC23.28 91.44,60.16 91.44,47.46 IC23.1 91.44,44.92 91.44,42.38 IC22.28 | IC20.16 48.25,34.76 50.79,37.3 50.79,37.94 BYP21.1 | v45.71,38.57 45.71,48.09 R7.2 | BYP28.1 66.67,84.29 67.94,84.29 IC28.16 68.58,83.02 68.58,80.48 67.31,79.21 67.31,74.13 68.58,72.86 IC19.16 68.58,70.32 69.84,69.05 69.84,41.11 71.12,39.84 IC21.8 | R6.2 86.36,50.63 88.9,48.09 88.9,41.74 BYP22.1 | v57.14,48.73 57.14,55.08 55.88,56.35 JP2.2
  Bottom 0.508: R14.2 17.78,6.18 19.05,7.46 19.68,7.46 IC24.20 21.59,8.09 24.12,10.63 34.28,10.63 IC24.22 | 19.05,78.58 22.22,78.58 24.76,81.11 IC17.36 | 19.05,78.58 15.23,78.58 13.33,76.67 R8.2 | 3.17,32.22 2.54,32.85 CORE-IO.9 | 3.17,32.22 4.44,30.95 CORE-IO.12 | 13.33,32.22 14.6,30.95 BYP26.1 | 13.33,32.22 3.17,32.22 | JP4.2 8.25,60.8 8.88,60.16 13.33,60.16 14.6,58.89 BYP25.1 15.87,58.89 17.14,60.16 19.05,60.16 | 28.57,61.43 32.38,65.24 33.02,65.24 IC17.8 | 27.3,60.16 28.57,61.43 | 27.3,60.16 26.03,58.89 BYP24.1 | 28.57,61.43 53.34,61.43 55.88,58.89 JP2.2 | 19.05,60.16 27.3,60.16 | 13.33,32.22 13.33,56.35 13.96,56.35 IC25.20 | 19.05,60.16 19.05,78.58 | IC24.24 34.92,16.34 21.59,29.68 17.78,29.68 16.51,28.41 IC26.20 | IC18.14 115.56,20.79 114.3,22.06 103.5,22.06 102.23,23.33 BYP17.1 | v81.28,15.71 77.47,15.71 IC27.4 | 86.36,13.17 85.09,13.17 IC27.10 | 86.36,13.17 93.34,13.17 95.25,11.27 105.41,11.27 106.04,10.63 BYP18.1 | 86.36,13.17 86.36,11.27 R12.2 | R1.2 98.42,20.79 95.88,23.33 85.09,23.33 IC27.14 | BYP23.1 86.99,61.43 90.8,61.43 IC23.28 92.07,60.8 93.34,60.8 IC23.27 | v45.71,38.57 50.16,38.57 BYP21.1 50.79,37.94 52.06,36.66 59.05,36.66 59.68,37.3 59.68,40.48 73.02,40.48 | BYP19.1 66.67,71.59 67.94,71.59 IC19.16 | 73.02,40.48 71.75,39.2 IC21.8 | 73.02,40.48 74.29,40.48 | 74.29,40.48 75.56,39.2 IC21.10 | 74.29,40.48 79.37,40.48 80.64,39.2 IC21.12 81.91,39.2 83.81,41.11 88.26,41.11 BYP22.1 89.53,41.11 90.8,41.11 IC22.28 | v57.14,48.73 46.35,48.73 R7.2
VMA  (via drill 0.61)
  Top 0.254: v74.93,73.5 74.93,46.19 72.39,43.65 v72.39,34.12 | v115.56,30.95 115.56,22.06 114.93,21.42 114.93,10 116.2,8.73 IC18.9
  Bottom 0.254: v74.93,73.5 32.38,73.5 26.03,67.14 IC17.5 | v72.39,34.12 75.56,30.95 v115.56,30.95

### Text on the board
Top: Component Side
Bottom: Solder side | PA8PDP/VRS
tPlace: RealConsole CORE - Rev.1 | 1 | 1 | 1 | 20 | 3 | 5 | 1 | + | 9 | 6 | 1 | 2,54 | 2 | F09 | 3
tNames: BYP29 | C2 | IC28 | Q1 | R5 | R8 | IC17 | IC29 | IC19 | JP4 | BYP23 | R13 | IC25 | IC24 | BYP25 | BYP24 | R7 | IC23 | R6 | BYP22 | IC21 | IC26 | BYP26 | C9 | IC22 | IC20 | BYP17 | IC27 | BYP27 | BYP20 | IC18 | COM | R1 | R12 | R3 | R2 | C3 | R14 | R4 | BYP18 | LED1 | C6 | R9 | R10 | R11
tValues: 27pf | .01uf | 74LS139N | 4Mhz | 6802 | 27256 | 3.3K | 3.3K | 74LS138N | - | .01uf | .01uf | .01uf | + | POWER | 1K | 74LS245N | 27C128P | 6821 | 3.3K | 6850 | 3.3K | .01uf | .01uf | TxD | 6264A | MAX232 | .01uf | 0.1uf | 74LS245N | LM556N | 10K | .01uf | 74LS132N | .01uf | 10K | 270 | 100K | 100K | 3.3K | .01uf | 22uf | 10K | 1.8K | 10K | 330pf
